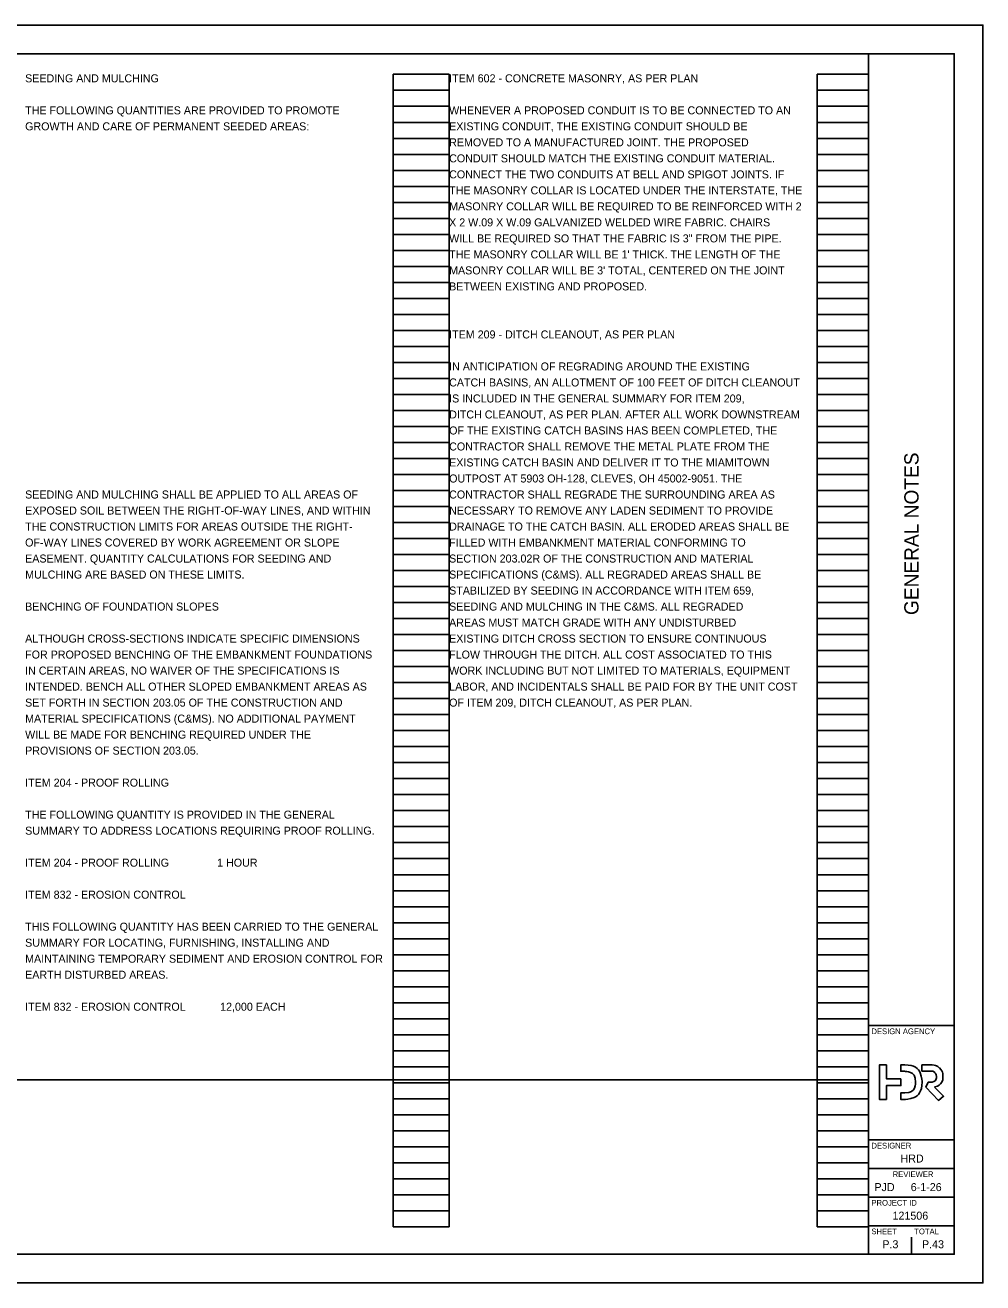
# Model space of a CAD drawing. Extents: x 0 to 34, y 0 to 22.
# Drawn here: x 17.24 to 34, y 0 to 22 of the extents above; entities that cross this region are included whole.
import ezdxf

# ---------------------------------------------------------------- set-up
doc = ezdxf.new("R2010")
doc.units = 0
for name, color, linetype in [('SH_Border', 7, 'Continuous'), ('SH_Cut_Line', 7, 'Continuous'), ('SH_Data', 7, 'Continuous'), ('SH_Text', 7, 'Continuous')]:
    doc.layers.add(name, color=color, linetype=linetype)

msp = doc.modelspace()

# ---------------------------------------------------------------- linework, layer by layer
at = {"layer": 'SH_Border'}
for p, q in [((32, 0.5), (32, 21.5)), ((32, 4.5), (33.5, 4.5)), ((32, 2.5), (33.5, 2.5)), ((32, 2), (33.5, 2)), ((32, 1.5), (33.5, 1.5)), ((32, 1), (33.5, 1))]:
    msp.add_line(p, q, dxfattribs=at)
msp.add_lwpolyline([(1.5, 21.5), (33.5, 21.5), (33.5, 0.5), (1.5, 0.5)], close=True, dxfattribs=at)
at = {"layer": 'SH_Cut_Line'}
msp.add_lwpolyline([(0, 0), (34, 0), (34, 22), (0, 22)], close=True, dxfattribs=at)
at = {"layer": 'SH_Data'}
for p, q in [((23.68, 0.98), (23.68, 21.14)), ((23.68, 21.14), (24.66, 21.14)), ((24.66, 0.98), (24.66, 21.14)), ((31.1, 0.98), (31.1, 21.14)), ((31.1, 21.14), (32, 21.14)), ((32, 0.98), (32, 21.14)), ((23.68, 20.86), (24.66, 20.86)), ((31.1, 20.86), (32, 20.86)), ((23.68, 20.58), (24.66, 20.58)), ((31.1, 20.58), (32, 20.58)), ((23.68, 20.3), (24.66, 20.3)), ((31.1, 20.3), (32, 20.3)), ((23.68, 20.02), (24.66, 20.02)), ((31.1, 20.02), (32, 20.02)), ((23.68, 19.74), (24.66, 19.74)), ((31.1, 19.74), (32, 19.74)), ((23.68, 19.46), (24.66, 19.46)), ((31.1, 19.46), (32, 19.46)), ((23.68, 19.18), (24.66, 19.18)), ((31.1, 19.18), (32, 19.18)), ((23.68, 18.9), (24.66, 18.9)), ((31.1, 18.9), (32, 18.9)), ((23.68, 18.62), (24.66, 18.62)), ((31.1, 18.62), (32, 18.62)), ((23.68, 18.34), (24.66, 18.34)), ((31.1, 18.34), (32, 18.34)), ((23.68, 18.06), (24.66, 18.06)), ((31.1, 18.06), (32, 18.06)), ((23.68, 17.78), (24.66, 17.78)), ((31.1, 17.78), (32, 17.78)), ((23.68, 17.5), (24.66, 17.5)), ((31.1, 17.5), (32, 17.5)), ((23.68, 17.22), (24.66, 17.22)), ((31.1, 17.22), (32, 17.22)), ((23.68, 16.94), (24.66, 16.94)), ((31.1, 16.94), (32, 16.94)), ((23.68, 16.66), (24.66, 16.66)), ((31.1, 16.66), (32, 16.66)), ((23.68, 16.38), (24.66, 16.38)), ((31.1, 16.38), (32, 16.38)), ((23.68, 16.1), (24.66, 16.1)), ((31.1, 16.1), (32, 16.1)), ((23.68, 15.82), (24.66, 15.82)), ((31.1, 15.82), (32, 15.82)), ((23.68, 15.54), (24.66, 15.54)), ((31.1, 15.54), (32, 15.54)), ((23.68, 15.26), (24.66, 15.26)), ((31.1, 15.26), (32, 15.26)), ((23.68, 14.98), (24.66, 14.98)), ((31.1, 14.98), (32, 14.98)), ((23.68, 14.7), (24.66, 14.7)), ((31.1, 14.7), (32, 14.7)), ((23.68, 14.42), (24.66, 14.42)), ((31.1, 14.42), (32, 14.42)), ((23.68, 14.14), (24.66, 14.14)), ((31.1, 14.14), (32, 14.14)), ((23.68, 13.86), (24.66, 13.86)), ((31.1, 13.86), (32, 13.86)), ((23.68, 13.58), (24.66, 13.58)), ((31.1, 13.58), (32, 13.58)), ((23.68, 13.3), (24.66, 13.3)), ((31.1, 13.3), (32, 13.3)), ((23.68, 13.02), (24.66, 13.02)), ((31.1, 13.02), (32, 13.02)), ((23.68, 12.74), (24.66, 12.74)), ((31.1, 12.74), (32, 12.74)), ((23.68, 12.46), (24.66, 12.46)), ((31.1, 12.46), (32, 12.46)), ((23.68, 12.18), (24.66, 12.18)), ((31.1, 12.18), (32, 12.18)), ((23.68, 11.9), (24.66, 11.9)), ((31.1, 11.9), (32, 11.9)), ((23.68, 11.62), (24.66, 11.62)), ((31.1, 11.62), (32, 11.62)), ((23.68, 11.34), (24.66, 11.34)), ((31.1, 11.34), (32, 11.34)), ((23.68, 11.06), (24.66, 11.06)), ((31.1, 11.06), (32, 11.06)), ((23.68, 10.78), (24.66, 10.78)), ((31.1, 10.78), (32, 10.78)), ((23.68, 10.5), (24.66, 10.5)), ((31.1, 10.5), (32, 10.5)), ((23.68, 10.22), (24.66, 10.22)), ((31.1, 10.22), (32, 10.22)), ((23.68, 9.94), (24.66, 9.94)), ((31.1, 9.94), (32, 9.94)), ((23.68, 9.66), (24.66, 9.66)), ((31.1, 9.66), (32, 9.66)), ((23.68, 9.38), (24.66, 9.38)), ((31.1, 9.38), (32, 9.38)), ((23.68, 9.1), (24.66, 9.1)), ((31.1, 9.1), (32, 9.1)), ((23.68, 8.82), (24.66, 8.82)), ((31.1, 8.82), (32, 8.82)), ((23.68, 8.54), (24.66, 8.54)), ((31.1, 8.54), (32, 8.54)), ((23.68, 8.26), (24.66, 8.26)), ((31.1, 8.26), (32, 8.26)), ((23.68, 7.98), (24.66, 7.98)), ((31.1, 7.98), (32, 7.98)), ((23.68, 7.7), (24.66, 7.7)), ((31.1, 7.7), (32, 7.7)), ((23.68, 7.42), (24.66, 7.42)), ((31.1, 7.42), (32, 7.42)), ((23.68, 7.14), (24.66, 7.14)), ((31.1, 7.14), (32, 7.14)), ((23.68, 6.86), (24.66, 6.86)), ((31.1, 6.86), (32, 6.86)), ((23.68, 6.58), (24.66, 6.58)), ((31.1, 6.58), (32, 6.58)), ((23.68, 6.3), (24.66, 6.3)), ((31.1, 6.3), (32, 6.3)), ((23.68, 6.02), (24.66, 6.02)), ((31.1, 6.02), (32, 6.02)), ((23.68, 5.74), (24.66, 5.74)), ((31.1, 5.74), (32, 5.74)), ((23.68, 5.46), (24.66, 5.46)), ((31.1, 5.46), (32, 5.46)), ((23.68, 5.18), (24.66, 5.18)), ((31.1, 5.18), (32, 5.18)), ((23.68, 4.9), (24.66, 4.9)), ((31.1, 4.9), (32, 4.9)), ((23.68, 4.62), (24.66, 4.62)), ((31.1, 4.62), (32, 4.62)), ((23.68, 4.34), (24.66, 4.34)), ((31.1, 4.34), (32, 4.34)), ((23.68, 4.06), (24.66, 4.06)), ((31.1, 4.06), (32, 4.06)), ((23.68, 3.78), (24.66, 3.78)), ((31.1, 3.78), (32, 3.78)), ((23.68, 3.5), (24.66, 3.5)), ((31.1, 3.5), (32, 3.5)), ((32.75, 3.5), (32.75, 3.5)), ((23.68, 3.22), (24.66, 3.22)), ((31.1, 3.22), (32, 3.22)), ((23.68, 2.94), (24.66, 2.94)), ((31.1, 2.94), (32, 2.94)), ((23.68, 2.66), (24.66, 2.66)), ((31.1, 2.66), (32, 2.66)), ((23.68, 2.38), (24.66, 2.38)), ((31.1, 2.38), (32, 2.38)), ((23.68, 2.1), (24.66, 2.1)), ((31.1, 2.1), (32, 2.1)), ((23.68, 1.82), (24.66, 1.82)), ((31.1, 1.82), (32, 1.82)), ((23.68, 1.54), (24.66, 1.54)), ((31.1, 1.54), (32, 1.54)), ((23.68, 1.26), (24.66, 1.26)), ((31.1, 1.26), (32, 1.26)), ((23.68, 0.98), (24.66, 0.98)), ((31.1, 0.98), (32, 0.98)), ((32.375, 0.675), (32.375, 0.675)), ((32.75, 0.5), (32.75, 0.8))]:
    msp.add_line(p, q, dxfattribs=at)
msp.add_lwpolyline([(32.565, 3.571), (32.311, 3.571), (32.311, 3.813), (32.189, 3.813), (32.189, 3.209), (32.311, 3.209), (32.311, 3.451), (32.565, 3.451)], close=True, dxfattribs=at)
for points in [[(32.634, 3.813), (32.562, 3.813), (32.562, 3.7), (32.634, 3.7)], [(33.063, 3.813), (32.935, 3.813), (32.935, 3.704), (33.072, 3.704)], [(32.634, 3.322), (32.562, 3.322), (32.562, 3.209), (32.634, 3.209)], [(32.936, 3.511), (32.936, 3.511), (32.936, 3.511), (32.936, 3.512), (32.936, 3.512)], [(33.077, 3.51), (33.043, 3.51), (33.003, 3.424), (33.226, 3.192), (33.313, 3.265), (33.155, 3.425)]]:
    msp.add_lwpolyline(points, dxfattribs=at)
for points in [[(32.936, 3.512), (32.936, 3.512), (32.935, 3.686), (32.808, 3.813), (32.634, 3.813)], [(33.239, 3.759), (33.239, 3.759), (33.193, 3.802), (33.141, 3.813), (33.063, 3.813)], [(33.302, 3.605), (33.302, 3.605), (33.302, 3.668), (33.284, 3.716), (33.239, 3.759)], [(32.634, 3.7), (32.634, 3.7), (32.744, 3.7), (32.822, 3.622), (32.822, 3.511)], [(33.072, 3.704), (33.072, 3.704), (33.113, 3.704), (33.141, 3.696), (33.161, 3.676)], [(33.189, 3.607), (33.189, 3.607), (33.189, 3.546), (33.136, 3.51), (33.077, 3.51)], [(33.155, 3.425), (33.155, 3.425), (33.242, 3.441), (33.302, 3.521), (33.302, 3.605)], [(33.161, 3.676), (33.161, 3.676), (33.179, 3.658), (33.189, 3.634), (33.189, 3.607)], [(32.822, 3.511), (32.822, 3.511), (32.822, 3.4), (32.744, 3.322), (32.634, 3.322)], [(32.634, 3.209), (32.634, 3.209), (32.808, 3.209), (32.935, 3.336), (32.936, 3.511)]]:
    msp.add_open_spline(points, degree=3, dxfattribs=at)
at = {"layer": 'SH_Text'}
msp.add_lwpolyline([(16.26, 3.553), (32, 3.553), (32, 0.5), (16.26, 0.5)], close=True, dxfattribs=at)

# ---------------------------------------------------------------- texts
at = {"layer": 'SH_Data'}
msp.add_text('GENERAL NOTES', height=0.25, rotation=90, dxfattribs=at).set_placement((32.875, 11.682))
for s, height, p in [('DESIGN AGENCY', 0.1, (32.05, 4.35)), ('DESIGNER', 0.1, (32.05, 2.35)), ('HRD', 0.14, (32.559, 2.105)), ('REVIEWER', 0.1, (32.422, 1.85)), ('PJD', 0.14, (32.103, 1.605)), ('6-1-26', 0.14, (32.738, 1.605)), ('PROJECT ID', 0.1, (32.05, 1.35)), ('121506', 0.14, (32.419, 1.105)), ('SHEET', 0.1, (32.05, 0.85)), ('TOTAL', 0.1, (32.8, 0.85)), ('P.3', 0.14, (32.241, 0.605)), ('P.43', 0.14, (32.935, 0.605))]:
    msp.add_text(s, height=height, dxfattribs=at).set_placement(p)
at = {"layer": 'SH_Text'}
for s, p in [('SEEDING AND MULCHING', (17.24, 21)), ('ITEM 602 - CONCRETE MASONRY, AS PER PLAN', (24.66, 21)), ('THE FOLLOWING QUANTITIES ARE PROVIDED TO PROMOTE', (17.24, 20.44)), ('WHENEVER A PROPOSED CONDUIT IS TO BE CONNECTED TO AN ', (24.66, 20.44)), ('GROWTH AND CARE OF PERMANENT SEEDED AREAS:', (17.24, 20.16)), ('EXISTING CONDUIT, THE EXISTING CONDUIT SHOULD BE', (24.66, 20.16)), ('REMOVED TO A MANUFACTURED JOINT. THE PROPOSED', (24.66, 19.88)), ('CONDUIT SHOULD MATCH THE EXISTING CONDUIT MATERIAL.', (24.66, 19.6)), ('CONNECT THE TWO CONDUITS AT BELL AND SPIGOT JOINTS. IF', (24.66, 19.32)), ('THE MASONRY COLLAR IS LOCATED UNDER THE INTERSTATE, THE ', (24.66, 19.04)), ('MASONRY COLLAR WILL BE REQUIRED TO BE REINFORCED WITH 2', (24.66, 18.76)), ('X 2 W.09 X W.09 GALVANIZED WELDED WIRE FABRIC. CHAIRS', (24.66, 18.48)), ('WILL BE REQUIRED SO THAT THE FABRIC IS 3" FROM THE PIPE.', (24.66, 18.2)), ("THE MASONRY COLLAR WILL BE 1' THICK. THE LENGTH OF THE ", (24.66, 17.92)), ("MASONRY COLLAR WILL BE 3' TOTAL, CENTERED ON THE JOINT", (24.66, 17.64)), ('BETWEEN EXISTING AND PROPOSED.', (24.66, 17.36)), ('ITEM 209 - DITCH CLEANOUT, AS PER PLAN', (24.66, 16.52)), ('IN ANTICIPATION OF REGRADING AROUND THE EXISTING', (24.66, 15.96)), ('CATCH BASINS, AN ALLOTMENT OF 100 FEET OF DITCH CLEANOUT ', (24.66, 15.68)), ('IS INCLUDED IN THE GENERAL SUMMARY FOR ITEM 209, ', (24.66, 15.4)), ('DITCH CLEANOUT, AS PER PLAN. AFTER ALL WORK DOWNSTREAM', (24.66, 15.12)), ('OF THE EXISTING CATCH BASINS HAS BEEN COMPLETED, THE', (24.66, 14.84)), ('CONTRACTOR SHALL REMOVE THE METAL PLATE FROM THE ', (24.66, 14.56)), ('EXISTING CATCH BASIN AND DELIVER IT TO THE MIAMITOWN', (24.66, 14.28)), ('OUTPOST AT 5903 OH-128, CLEVES, OH 45002-9051. THE ', (24.66, 14)), ('SEEDING AND MULCHING SHALL BE APPLIED TO ALL AREAS OF', (17.24, 13.72)), ('CONTRACTOR SHALL REGRADE THE SURROUNDING AREA AS', (24.66, 13.72)), ('EXPOSED SOIL BETWEEN THE RIGHT-OF-WAY LINES, AND WITHIN', (17.24, 13.44)), ('NECESSARY TO REMOVE ANY LADEN SEDIMENT TO PROVIDE', (24.66, 13.44)), ('THE CONSTRUCTION LIMITS FOR AREAS OUTSIDE THE RIGHT-', (17.24, 13.16)), ('DRAINAGE TO THE CATCH BASIN. ALL ERODED AREAS SHALL BE ', (24.66, 13.16)), ('OF-WAY LINES COVERED BY WORK AGREEMENT OR SLOPE', (17.24, 12.88)), ('FILLED WITH EMBANKMENT MATERIAL CONFORMING TO', (24.66, 12.88)), ('EASEMENT. QUANTITY CALCULATIONS FOR SEEDING AND', (17.24, 12.6)), ('SECTION 203.02R OF THE CONSTRUCTION AND MATERIAL', (24.66, 12.6)), ('MULCHING ARE BASED ON THESE LIMITS.', (17.24, 12.32)), ('SPECIFICATIONS (C&MS). ALL REGRADED AREAS SHALL BE ', (24.66, 12.32)), ('STABILIZED BY SEEDING IN ACCORDANCE WITH ITEM 659,', (24.66, 12.04)), ('BENCHING OF FOUNDATION SLOPES', (17.24, 11.76)), ('SEEDING AND MULCHING IN THE C&MS. ALL REGRADED', (24.66, 11.76)), ('AREAS MUST MATCH GRADE WITH ANY UNDISTURBED', (24.66, 11.48)), ('ALTHOUGH CROSS-SECTIONS INDICATE SPECIFIC DIMENSIONS', (17.24, 11.2)), ('EXISTING DITCH CROSS SECTION TO ENSURE CONTINUOUS', (24.66, 11.2)), ('FOR PROPOSED BENCHING OF THE EMBANKMENT FOUNDATIONS', (17.24, 10.92)), ('FLOW THROUGH THE DITCH. ALL COST ASSOCIATED TO THIS', (24.66, 10.92)), ('IN CERTAIN AREAS, NO WAIVER OF THE SPECIFICATIONS IS', (17.24, 10.64)), ('WORK INCLUDING BUT NOT LIMITED TO MATERIALS, EQUIPMENT', (24.66, 10.64)), ('INTENDED. BENCH ALL OTHER SLOPED EMBANKMENT AREAS AS', (17.24, 10.36)), ('LABOR, AND INCIDENTALS SHALL BE PAID FOR BY THE UNIT COST', (24.66, 10.36)), ('SET FORTH IN SECTION 203.05 OF THE CONSTRUCTION AND', (17.24, 10.08)), ('OF ITEM 209, DITCH CLEANOUT, AS PER PLAN.', (24.66, 10.08)), ('MATERIAL SPECIFICATIONS (C&MS). NO ADDITIONAL PAYMENT', (17.24, 9.8)), ('WILL BE MADE FOR BENCHING REQUIRED UNDER THE', (17.24, 9.52)), ('PROVISIONS OF SECTION 203.05.', (17.24, 9.24)), ('ITEM 204 - PROOF ROLLING', (17.24, 8.68)), ('THE FOLLOWING QUANTITY IS PROVIDED IN THE GENERAL', (17.24, 8.12)), ('SUMMARY TO ADDRESS LOCATIONS REQUIRING PROOF ROLLING.', (17.24, 7.84)), ('ITEM 204 - PROOF ROLLING', (17.24, 7.28)), ('1 HOUR', (20.6, 7.28)), ('ITEM 832 - EROSION CONTROL', (17.24, 6.72)), ('THIS FOLLOWING QUANTITY HAS BEEN CARRIED TO THE GENERAL', (17.24, 6.16)), ('SUMMARY FOR LOCATING, FURNISHING, INSTALLING AND', (17.24, 5.88)), ('MAINTAINING TEMPORARY SEDIMENT AND EROSION CONTROL FOR', (17.24, 5.6)), ('EARTH DISTURBED AREAS.', (17.24, 5.32)), ('ITEM 832 - EROSION CONTROL', (17.24, 4.76)), (' 12,000 EACH', (20.6, 4.76))]:
    msp.add_text(s, height=0.14, dxfattribs=at).set_placement(p)

doc.saveas('drawing.dxf')
